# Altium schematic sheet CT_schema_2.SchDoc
size 297 x 173 mm
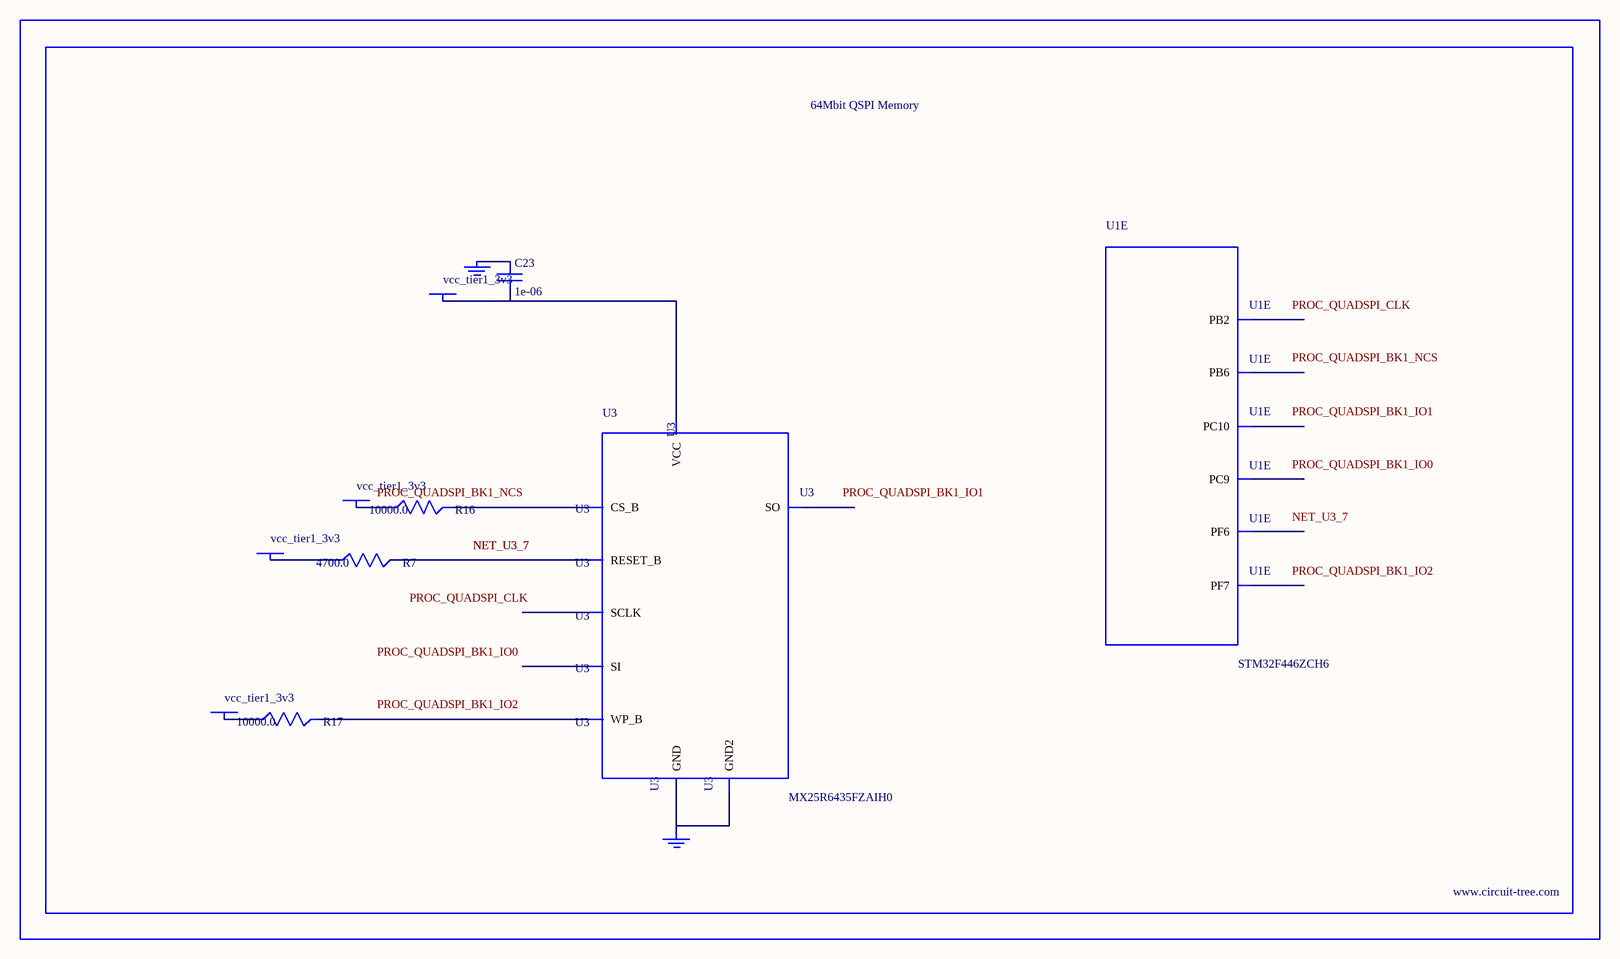
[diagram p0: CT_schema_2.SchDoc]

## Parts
BORDER1  (no value)
C23  1e-06  [C0603]
GND_INSTANCE_1_0  (no value)
GND_INSTANCE_1_1  (no value)
POWER_INSTANCE_1_0  vcc_tier1_3v3
POWER_INSTANCE_1_1  vcc_tier1_3v3
POWER_INSTANCE_1_2  vcc_tier1_3v3
POWER_INSTANCE_1_3  vcc_tier1_3v3
R7  4700.0  [R0603]
R16  10000.0  [R0603]
R17  10000.0  [R0603]
U1  STM32F446ZCH6  [UFBGA144]  (part E of 11)
U3  MX25R6435FZAIH0  [WSON-8-PAD]

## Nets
NetC23_1: C23.1 GND_INSTANCE_1_0.0(GND)
NetC23_2: C23.2 POWER_INSTANCE_1_2.0(PWR) U3.8(VCC)
NetGND_INSTANCE_1_1_0: GND_INSTANCE_1_1.0(GND) U3.4(GND) U3.PAD(GND2)
NetPOWER_INSTANCE_1_0_0: POWER_INSTANCE_1_0.0(PWR) R16.1
NetPOWER_INSTANCE_1_1_0: POWER_INSTANCE_1_1.0(PWR) R17.1
NetPOWER_INSTANCE_1_3_0: POWER_INSTANCE_1_3.0(PWR) R7.1
NetR7_2: R7.2 U3.7(RESET_B)
NetR16_2: R16.2 U3.1(CS_B)
NetR17_2: R17.2 U3.3(WP_B)

Not connected (* = marked no-connect by the designer): U1 B11(PC10) C6(PB6) E11(PC9) F2(PF7) F3(PF6) J5(PB2); U3 2(SO) 5(SI) 6(SCLK)

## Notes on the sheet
- Labels drawn without touching a wire or pin: NET_U3_7, PROC_QUADSPI_BK1_IO0, PROC_QUADSPI_BK1_IO1, PROC_QUADSPI_BK1_IO2, PROC_QUADSPI_BK1_NCS, PROC_QUADSPI_CLK

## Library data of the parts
BORDER1 = BORDER_PAGE1
C23 = C0603C105K3RACTU
GND_INSTANCE_1_0 GND_INSTANCE_1_1 = GND
POWER_INSTANCE_1_0-POWER_INSTANCE_1_3 = PWR
R7 = RC0603JR-074K7L
R16 R17 = RC0603JR-0710KL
